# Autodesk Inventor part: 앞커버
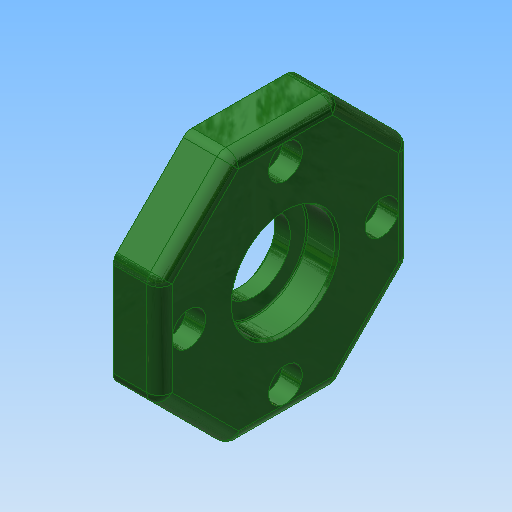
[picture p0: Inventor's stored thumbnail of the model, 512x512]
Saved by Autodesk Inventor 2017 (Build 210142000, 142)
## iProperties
Created: 2015-11
Part Number: 앞커버
Material: 알루미늄 6061
Document SubType Name: Modeling
Designer: mduedu
Density: 1 g/cm^3
Appearance: 매끄러움 - 짙은 산림 녹색
Author: mduedu
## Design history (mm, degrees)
sketch "스케치5" dims "d66" = 60
  geometry: L1 (12.426, 30)-(30, 12.426); L2 (30, 12.426)-(30, -12.426); L3 (30, -12.426)-(12.426, -30); L4 (12.426, -30)-(-12.426, -30); L5 (-12.426, -30)-(-30, -12.426); L6 (-30, -12.426)-(-30, 12.426); L7 (-30, 12.426)-(-12.426, 30); L8 (-12.426, 30)-(12.426, 30); 4 further points
  constraints: 16 end point, 2 coincident, 2 vertical alignment, 1 midpoint, 19 other
extrude "돌출2" new body sketch "스케치5" distance "d67" = 11; taper "d68" = 0 deg
sketch "스케치6"
  geometry: C1 r 16 at (0, 0); 1 further point
  constraints: 1 centre point, 1 coincident
  dimensions: "d69" = 32 diameter of C1
extrude "돌출3" join sketch "스케치6" distance "d70" = 3; taper "d71" = 0 deg
hole "구멍7" diameter "d98" = 25; stored, may be unused: countersink angle "d102" = 90 deg, drill point angle "d104" = 0 deg; dims "d96" = 10, "d97" = 10, "d99" = 6, "d100" = 4, "d101" = 2, "d103" = 3
hole "구멍8" diameter "d107" = 25; stored, may be unused: countersink angle "d111" = 90 deg, drill point angle "d113" = 0 deg; dims "d108" = 6, "d109" = 4, "d110" = 2, "d112" = 7.3, "d143" = 10, "d144" = 10
hole "구멍9" diameter "d116" = 17; stored, may be unused: countersink angle "d120" = 90 deg, drill point angle "d122" = 0 deg; dims "d114" = 10, "d115" = 10, "d117" = 6, "d118" = 4, "d119" = 2, "d121" = 7.7
chamfer "모따기2" distance "d123" = 0.7; stored, may be unused: second distance "d124" = 2, angle "d125" = 30 deg
fillet "모깎기11" dims "d126" = 0.3
fillet "모깎기12" dims "d127" = 3
fillet "모깎기13" dims "d128" = 3
fillet "모깎기14" dims "d129" = 3
fillet "모깎기15" dims "d130" = 0.3
sketch "스케치8" dims "d131" = 46
  geometry: 3 further points
  constraints: 2 vertical alignment, 1 coincident, 2 other
hole "구멍10" sketch "스케치8" at (0, 23) diameter "d132" = 4.5; stored, may be unused: countersink angle "d136" = 90 deg, drill point angle "d138" = 0 deg; dims "d133" = 6, "d134" = 8, "d135" = 4.6, "d137" = 7.7
node "솔리드2"
pattern_circular "원형 패턴4" dims angle "d140" = 360 deg
